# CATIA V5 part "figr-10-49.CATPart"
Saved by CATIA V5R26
Part number: Part1
Bounding box of the stored display mesh (mm): x -75 to 75, y 0 to 282.665, z -39.154 to 114.529
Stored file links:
  D:\_Deepak\CATIA\CATIA V5-6R2016_Deepak\Resources\Part files\Partfiles\c10_catia_v5_6r2016_prt\figr-10-49.CATPart
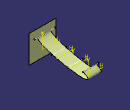
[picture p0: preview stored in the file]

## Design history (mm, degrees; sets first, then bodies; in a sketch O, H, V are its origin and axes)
Body1 (main body)
  Plane1: type Offset, RefPlane zx-plane, Offset 85
  Sketch1 on yz-plane, origin (0, 0, 0), H (0, 1, 0), V (0, 0, 1)
    line L1 (0, 114.5286) -> (0, -39.1536)
    point P1 (0, 114.5286)
    coincidence: P1 V
    vertical: L1 V
  Extrude1: Lim1 75, Lim2 75, Element1 Sketch1
  Plane2: type Offset, RefPlane Plane1, Offset 85
  Plane3: type Offset, RefPlane Plane2, Offset 85
  Sketch2 on zx-plane, origin (0, 0, 0), H (-1, 0, 0), V (0, 0, 1)
    line L1 (-43.9118, 70.4151) -> (71.5537, 70.4151)
    horizontal: L1 H
  Sketch3 on Plane1, origin (0, 85, 0), H (-1, 0, 0), V (0, 0, 1)
    line L1 (-29.1778, 30.4555) -> (46.4999, 30.4555)
    horizontal: L1 H
  Sketch4 on Plane2, origin (0, 170, 0), H (-1, 0, 0), V (0, 0, 1)
    line L1 (-27.284, 11.606) -> (54.5029, 11.606)
    horizontal: L1 H
  Sketch5 on Plane3, origin (0, 255, 0), H (-1, 0, 0), V (0, 0, 1)
    line L1 (-28.2106, 33.1442) -> (56.8447, 33.1442)
    horizontal: L1 H
  Sweep1: type Conic, Guide ({sweepconicextendedguide Guide Sketch2, Reference zx-plane, Angle 0}; Sketch3; Sketch4; Sketch5)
